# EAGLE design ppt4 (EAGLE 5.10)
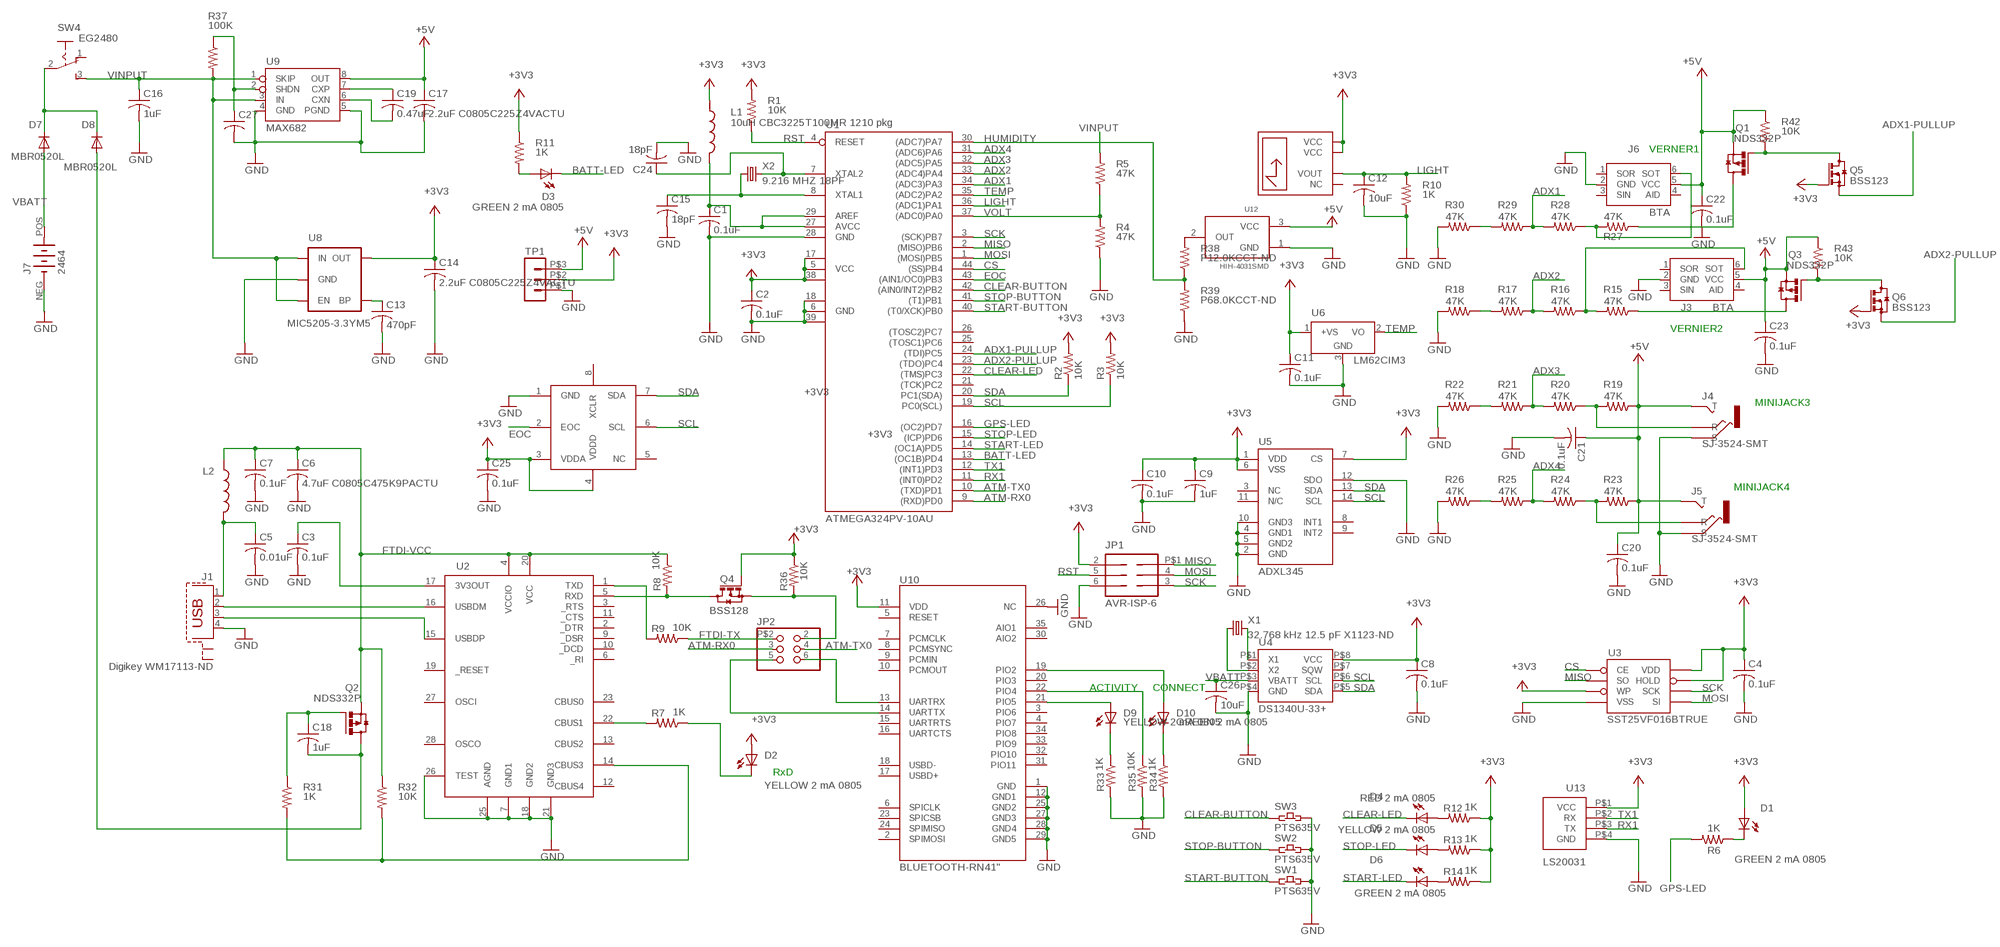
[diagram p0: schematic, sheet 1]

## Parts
C1  0.1uF  C-USC0805  [C0805]
C2  0.1uF  C-USC0805  [C0805]
C3  0.1uF  C-USC0805  [C0805]
C4  0.1uF  C-USC0805  [C0805]
C5  0.01uF  C-USC0805  [C0805]
C6  4.7uF C0805C475K9PACTU  C-USC0805  [C0805]
C7  0.1uF  C-USC0805  [C0805]
C8  0.1uF  C-USC0805  [C0805]
C9  1uF  C-USC0805  [C0805]
C10  0.1uF  C-USC0805  [C0805]
C11  0.1uF  C-USC0805  [C0805]
C12  10uF  C-USC0805  [C0805]
C13  470pF  C-USC0805  [C0805]
C14  2.2uF C0805C225Z4VACTU  C-USC0805  [C0805]
C15  18pF  C-USC1206K  [C1206K]
C16  1uF  C-USC0805  [C0805]
C17  2.2uF C0805C225Z4VACTU  C-USC0805  [C0805]
C18  1uF  C-USC0805  [C0805]
C19  0.47uF  C-USC0805  [C0805]
C20  0.1uF  C-USC0805  [C0805]
C21  0.1uF  C-USC0805  [C0805]
C22  0.1uF  C-USC0805  [C0805]
C23  0.1uF  C-USC0805  [C0805]
C24  18pF  C-USC1206K  [C1206K]
C25  0.1uF  C-USC0805  [C0805]
C26  10uF  C-USC0805  [C0805]
C27  C-USC0805  [C0805]
D1  GREEN 2 mA 0805  LED_MS  [LED-0805]
D2  YELLOW 2 mA 0805  LED_MS  [LED-0805]
D3  GREEN 2 mA 0805  LED_MS  [LED-0805]
D4  RED 2 mA 0805  LED_MS  [LED-0805]
D5  YELLOW 2 mA 0805  LED_MS  [LED-0805]
D6  GREEN 2 mA 0805  LED_MS  [LED-0805]
D7  MBR0520L  MBR0520LT  [SOD123]
D8  MBR0520L  MBR0520LT  [SOD123]
D9  YELLOW 2 mA 0805  LED_MS  [LED-0805]
D10  GREEN 2 mA 0805  LED_MS  [LED-0805]
J1  Digikey WM17113-ND  PN61729-S  [PN61729-S]
J3  BTA  DIY164  [DY164]
J4  SJ-3524-SMT  [SJ-3534-SMT]
J5  SJ-3524-SMT  [SJ-3534-SMT]
J6  BTA  DIY164  [DY164]
J7  2464  [2464R]
JP1  AVR-ISP-6  [AVR-ISP-6]
JP2  PINHD-2X3  [2X03]
L1  10uH CBC3225T100MR 1210 pkg  L-USL3216C  [L3216C]
L2  10uH CBC3225T100MR 1210 pkg  L-USL3216C  [L3216C]
Q1  NDS332P  FDN360P  [SUPER-SOT3]
Q2  NDS332P  FDN360P  [SUPER-SOT3]
Q3  NDS332P  FDN360P  [SUPER-SOT3]
Q4  BSS128  BSS123  [SOT23]
Q5  BSS123  [SOT23]
Q6  BSS123  [SOT23]
R1  10K  R-US_R0805  [R0805]
R2  10K  R-US_R0805  [R0805]
R3  10K  R-US_R0805  [R0805]
R4  47K  R-US_R0805  [R0805]
R5  47K  R-US_R0805  [R0805]
R6  1K  R-US_R0805  [R0805]
R7  1K  R-US_R0805  [R0805]
R8  10K  R-US_R0805  [R0805]
R9  10K  R-US_R0805  [R0805]
R10  1K  R-US_R0805  [R0805]
R11  1K  R-US_R0805  [R0805]
R12  1K  R-US_R0805  [R0805]
R13  1K  R-US_R0805  [R0805]
R14  1K  R-US_R0805  [R0805]
R15  47K  R-US_R0805  [R0805]
R16  47K  R-US_R0805  [R0805]
R17  47K  R-US_R0805  [R0805]
R18  47K  R-US_R0805  [R0805]
R19  47K  R-US_R0805  [R0805]
R20  47K  R-US_R0805  [R0805]
R21  47K  R-US_R0805  [R0805]
R22  47K  R-US_R0805  [R0805]
R23  47K  R-US_R0805  [R0805]
R24  47K  R-US_R0805  [R0805]
R25  47K  R-US_R0805  [R0805]
R26  47K  R-US_R0805  [R0805]
R27  47K  R-US_R0805  [R0805]
R28  47K  R-US_R0805  [R0805]
R29  47K  R-US_R0805  [R0805]
R30  47K  R-US_R0805  [R0805]
R31  1K  R-US_R0805  [R0805]
R32  10K  R-US_R0805  [R0805]
R33  1K  R-US_R0805  [R0805]
R34  1K  R-US_R0805  [R0805]
R35  10K  R-US_R0805  [R0805]
R36  10K  R-US_R0805  [R0805]
R37  100K  R-US_R0805  [R0805]
R38  P12.0KCCT-ND  R-US_R0805  [R0805]
R39  P68.0KCCT-ND  R-US_R0805  [R0805]
R42  10K  R-US_R0805  [R0805]
R43  10K  R-US_R0805  [R0805]
SW1  PTS635V  [PTS635V]
SW2  PTS635V  [PTS635V]
SW3  PTS635V  [PTS635V]
SW4  EG2480  SLIDE_SWITCH-VERT  [102-1271-EV]
TP1  MA03-1  [MA03-1]
U1  ATMEGA324PV-10AU  MEGA32-A  [TQFP44]
U2  FT232RL  [SSOP28DB]
U3  SST25VF016BTRUE  [WSON]
U4  DS1340U-33+  DS1307  [UMAX-8]
U5  ADXL345  [LGA14]
U6  LM62CIM3  LM50  [SOT23]
U7  APDS-9002  [APDS-9002]
U8  MIC5205-3.3YM5  V_REG_LDOSMD  [SOT23-5]
U9  MAX682  [SO08]
U10  BLUETOOTH-RN41"  [RN41]
U11  BMP085  [BMP085]
U12  HIH-4031SMD  HIH-4030SMD  [HIH-4030]
U13  LS20031  [DF3A-4P-BACK]
X1  32.768 kHz 12.5 pF X1123-ND  CRYSTALTC26H  [TC26H]
X2  9.216 MHZ 18PF  CRYSTALHC49U-V  [HC49U-V]

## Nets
+3V3 [SUPPLY]: C2.1 C4.1 C8.1 C9.1 C10.1 C11.1 C14.1 C25.1 D1.A D2.A JP1.2(VTG) L1.1 Q4.1(G) Q5.1(G) Q6.1(G) R1.2 R2.2 R3.2 R11.1 R12.1 R13.1 R14.1 R36.1 TP1.P$2 U1.5(VCC) U1.17(VCC1) U1.38(VCC2) U3.HOLD#(HOLD) U3.VDD U3.WP#(WP) U4.P$8(VCC) U5.1(VDD) U5.6(VSS) U5.7(CS) U6.1(+VS) U7.2(VCC) U7.3(VCC) U8.5(OUT) U10.11(VDD) U11.3(VDDA) U11.4(VDDD) U13.P$1(VCC)
+5V [SUPPLY]: C17.1 C20.1 C21.1 C22.1 C23.1 J3.5(VCC) J4.2(T) J5.2(T) J6.5(VCC) Q1.2(S) Q3.2(S) R19.1 R23.1 R42.1 R43.1 TP1.P$3 U9.8(OUT) U12.3(VCC)
ADX1: R28.2 R29.1 U1.34((ADC3)PA3)
ADX1-PULLUP: Q5.2(S) U1.24((TDI)PC5)
ADX2: R16.2 R17.1 U1.33((ADC4)PA4)
ADX2-PULLUP: Q6.2(S) U1.23((TDO)PC4)
ADX3: R20.2 R21.1 U1.32((ADC5)PA5)
ADX4: R24.2 R25.1 U1.31((ADC6)PA6)
ATM-RX0: JP2.3 U1.9((RXD)PD0)
ATM-TX0: JP2.4 U1.10((TXD)PD1)
BATT-LED: D3.C U1.13((OC1B)PD4)
CLEAR-BUTTON: SW3.1 U1.42((AIN0/INT2)PB2)
CLEAR-LED: D4.C U1.22((TMS)PC3)
CS: U1.44((SS)PB4) U3.CE#(CE)
EOC: U1.43((AIN1/OC0)PB3) U11.2(EOC)
FTDI-RX: JP2.2 Q4.2(S) R36.2
FTDI-TX: JP2.P$2 R9.1
FTDI-VCC [SUPPLY]: C6.1 C7.1 L2.1 Q2.2(S) R8.1 R32.1 U2.4(VCCIO) U2.20(VCC)
GND [SUPPLY]: C1.2 C2.2 C3.2 C4.2 C5.2 C6.2 C7.2 C8.2 C9.2 C10.2 C11.2 C12.2 C13.2 C14.2 C15.2 C16.2 C17.2 C20.2 C21.2 C22.2 C23.2 C24.2 C25.2 C26.2 C27.2 J1.4 J3.2(GND) J4.1(S) J5.1(S) J6.2(GND) J7.NEG(-) JP1.6(GND) R4.1 R10.1 R18.2 R22.2 R26.2 R30.2 R33.2 R34.2 R35.2 R39.1 SW1.2 SW2.2 SW3.2 TP1.P$1 U1.6(GND) U1.18(GND1) U1.28(GND) U1.39(GND2) U2.7(GND1) U2.18(GND2) U2.21(GND3) U2.25(AGND) U2.26(TEST) U3.VSS U4.P$4(GND) U5.2(GND) U5.4(GND1) U5.5(GND2) U5.10(GND3) U5.12(SDO) U6.3(GND) U8.2(GND) U9.4(GND) U9.5(PGND) U10.1(GND) U10.12(GND1) U10.25(GND2) U10.26(NC) U10.27(GND3) U10.28(GND4) U10.29(GND5) U11.1(GND) U12.1(GND) U13.P$4(GND)
GPS-LED: R6.2 U1.16((OC2)PD7)
HUMIDITY: R38.1 R39.2 U1.30((ADC7)PA7)
LIGHT: C12.1 R10.2 U1.36((ADC1)PA1) U7.1(VOUT)
MISO: JP1.P$1(MISO) U1.2((MISO)PB6) U3.SO
MOSI: JP1.4(MOSI) U1.1((MOSI)PB5) U3.SI
N$1: J1.2 U2.16(USBDM)
N$2: J1.3 U2.15(USBDP)
N$3: C1.1 L1.2 U1.27(AVCC) U1.29(AREF)
N$4: R38.2 U12.2(OUT)
N$5: D9.C R33.1
N$6: D3.A R11.2
N$7 [SUPPLY]: C5.1 J1.1 L2.2
N$8 [SUPPLY]: D1.C R6.1
N$9: R7.2 U2.22(CBUS1)
N$10 [SUPPLY]: D2.C R7.1
N$11: Q4.3(D) R8.2 U2.5(RXD)
N$12: R9.2 U2.1(TXD)
N$13 [SUPPLY]: C3.1 U2.17(3V3OUT)
N$14: U4.P$1(X1) X1.2
N$15: U4.P$2(X2) X1.1
N$16: D4.A R12.2
N$17: D5.A R13.2
N$18: D6.A R14.2
N$19: J3.6(SOT) R15.2 R16.1
N$20: J6.6(SOT) R27.2 R28.1
N$21: R17.2 R18.1
N$22: J4.3(R) R19.2 R20.1
N$23: R29.2 R30.1
N$24: R21.2 R22.1
N$25: J5.3(R) R23.2 R24.1
N$26: C13.1 U8.4(BP)
N$27: R25.2 R26.1
N$28 [SUPPLY]: C19.1 U9.7(CXP)
N$29 [SUPPLY]: C18.1 Q2.1(G) R31.1
N$30 [SUPPLY]: C19.2 U9.6(CXN)
N$31 [SUPPLY]: C18.2 D8.A Q2.3(D)
N$32: Q1.3(D) R27.1
N$33: C24.1 U1.7(XTAL2) X2.2
N$34: C27.1 R37.1 U9.2(SHDN)
N$35: C15.1 U1.8(XTAL1) X2.1
N$36: D9.A U10.21(PIO5)
N$37: D10.C R34.1
N$38: D10.A U10.19(PIO2)
N$39: R35.1 U10.22(PIO4)
N$40: Q1.1(G) Q5.3(D) R42.2
N$41: Q3.3(D) R15.1
N$42: Q3.1(G) Q6.3(D) R43.2
PWREN~ [SUPPLY]: R31.2 R32.2 U2.14(CBUS3)
RST: JP1.5(RST) R1.1 U1.4(RESET)
RX1: U1.11((INT0)PD2) U13.P$3(TX)
RX-BT: JP2.5 U10.14(UARTTX)
SCK: JP1.3(SCK) U1.3((SCK)PB7) U3.SCK
SCL: R3.1 U1.19(PC0(SCL)) U4.P$6(SCL) U5.14(SCL) U11.6(SCL)
SDA: R2.1 U1.20(PC1(SDA)) U4.P$5(SDA) U5.13(SDA) U11.7(SDA)
START-BUTTON: SW1.1 U1.40((T0/XCK)PB0)
START-LED: D6.C U1.14((OC1A)PD5)
STOP-BUTTON: SW2.1 U1.41((T1)PB1)
STOP-LED: D5.C U1.15((ICP)PD6)
TEMP: U1.35((ADC2)PA2) U6.2(VO)
TX1: U1.12((INT1)PD3) U13.P$2(RX)
TX-BT: JP2.6 U10.13(UARTRX)
UNSWPWR [SUPPLY]: D7.C D8.C SW4.2(COM)
VBATT [SUPPLY]: C26.1 D7.A J7.POS(+) U4.P$3(VBATT)
VINPUT [SUPPLY]: C16.1 R5.2 R37.2 SW4.3 U8.1(IN) U8.3(EN) U9.1(SKIP) U9.3(IN)
VOLT: R4.2 R5.1 U1.37((ADC0)PA0)
Unconnected: J1.S1 J1.S2 J3.1(SOR) J3.3(SIN) J3.4(AID) J6.1(SOR) J6.3(SIN) J6.4(AID) SW4.1 U1.21((TCK)PC2) U1.25((TOSC1)PC6) U1.26((TOSC2)PC7) U2.2(_DTR) U2.3(_RTS) U2.6(_RI) U2.9(_DSR) U2.10(_DCD) U2.11(_CTS) U2.12(CBUS4) U2.13(CBUS2) U2.19(_RESET) U2.23(CBUS0) U2.27(OSCI) U2.28(OSCO) U4.P$7(SQW) U5.3(NC) U5.8(INT1) U5.9(INT2) U5.11(N/C) U7.4(NC) U10.2(SPIMOSI) U10.3(PIO6) U10.4(PIO7) U10.5(RESET) U10.6(SPICLK) U10.7(PCMCLK) U10.8(PCMSYNC) U10.9(PCMIN) U10.10(PCMOUT) U10.15(UARTRTS) U10.16(UARTCTS) U10.17(USBD+) U10.18(USBD-) U10.20(PIO3) U10.23(SPICSB) U10.24(SPIMISO) U10.30(AIO2) U10.31(PIO11) U10.32(PIO10) U10.33(PIO9) U10.34(PIO8) U10.35(AIO1) U11.5(NC) U11.8(XCLR)

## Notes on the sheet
- VERNER1
- VERNIER2
- MINIJACK3
- MINIJACK4
- ACTIVITY | CONNECT
- RxD

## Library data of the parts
C1-C27 = rcl:C-US: CAPACITOR, American symbol
D1-D6 D9 D10 = machine_science:LED_MS
D7 D8 = diode:MBR0520LT: SCHOTTKY BARRIER RECTIFIER
J1 = con-berg:PN61729-S: BERG USB connector
J3 J6 = machine_science2:DIY164
J4 J5 = machine_science2:SJ-3524-SMT
J7 = machine_science2:2464
JP1 = machine_science:AVR-ISP-6: AVR ISP-6 Serial Programming Header
JP2 = pinhead:PINHD-2X3: PIN HEADER
L1 L2 = rcl:L-US: INDUCTOR, American symbol
Q1-Q3 = transistor-power:FDN360P: Single P-Channel, PowerTrench (R) MOSFET Source: http://www.fairchildsemi.com/ds/FD/FDN360P.pdf
Q4-Q6 = transistor-small-signal:BSS123: N-CHANNEL MOS FET
R1-R39 R42 R43 = rcl:R-US_: RESISTOR, American symbol
SW1-SW3 = machine_science:PTS635
SW4 = machine_science:SLIDE_SWITCH
TP1 = con-lstb:MA03-1: PIN HEADER
U1 = atmel:MEGA32: MICROCONTROLLER 32 Kbytes FLASH 2 Kbytes SRAM 1 Kbytes EEPROM USART 8-channel 10 bit ADC Source: www.atmel.com .. doc2503.pdf
U2 = SparkFunEagle-6-6-07:FT232RL: USB UART FT232RL 4th Generation USB UART (USB <-> Serial) Controller. Spark Fun Electronics SKU : COM-00650
U3 = machine_science:SST25VF016BTRUE
U4 = SparkFun:DS1307
U5 = SparkFun:ADXL345
U6 = linear:LM50: SOT-23 Single-Supply Centigrade Temperature Sensor Vout = (10mV/°C x Temp °C) +5mmmV Source: http://cache.national.com/ds/LM/LM50.pdf
U7 = machine_science:APDS-9002
U8 = SparkFun:V_REG_LDO: Voltage Regulator LDO Standard 150mA LDO voltage regulator in SOT-23 layout. Micrel part MIC5205. BP (by-pass) pin is used to lower output noise with 470pF cap.
U9 = max682:MAX682
U10 = SparkFun:BLUETOOTH-RN41
U11 = SparkFun-20100301:BMP085
U12 = SparkFun-20100301:HIH-4030: Humidity Sensor
U13 = machine_science:LS20031
X1 = SparkFun:CRYSTAL: Crystals
X2 = crystal:CRYSTAL: CRYSTAL

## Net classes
0 SIGNAL: width 0.203 mm, drill 0.203 mm, clearance 0.203 mm
1 SUPPLY: width 0.356 mm, drill 0.203 mm, clearance 0.203 mm

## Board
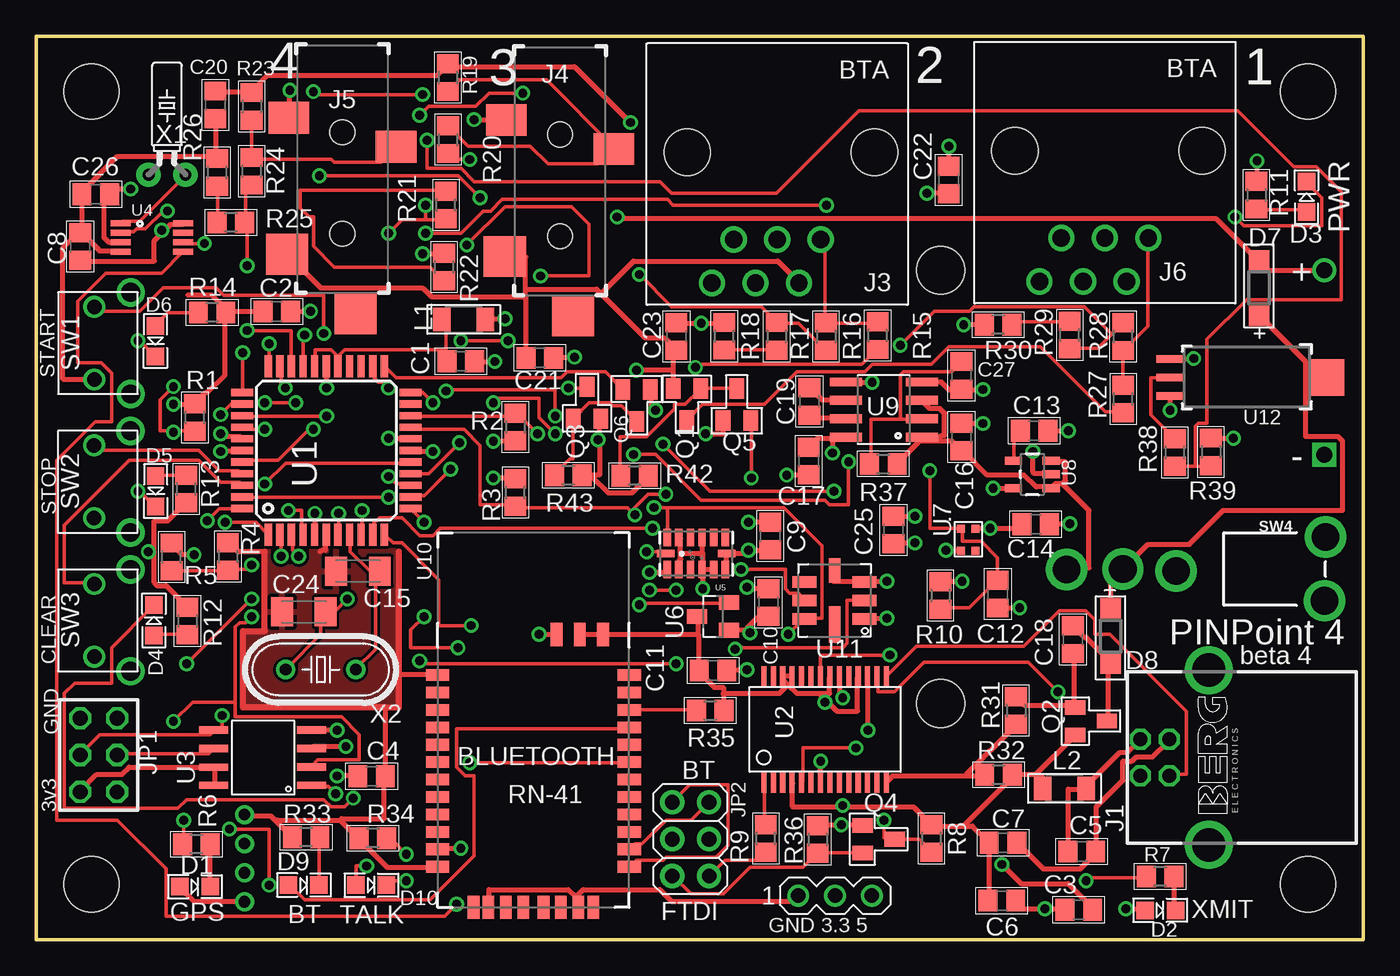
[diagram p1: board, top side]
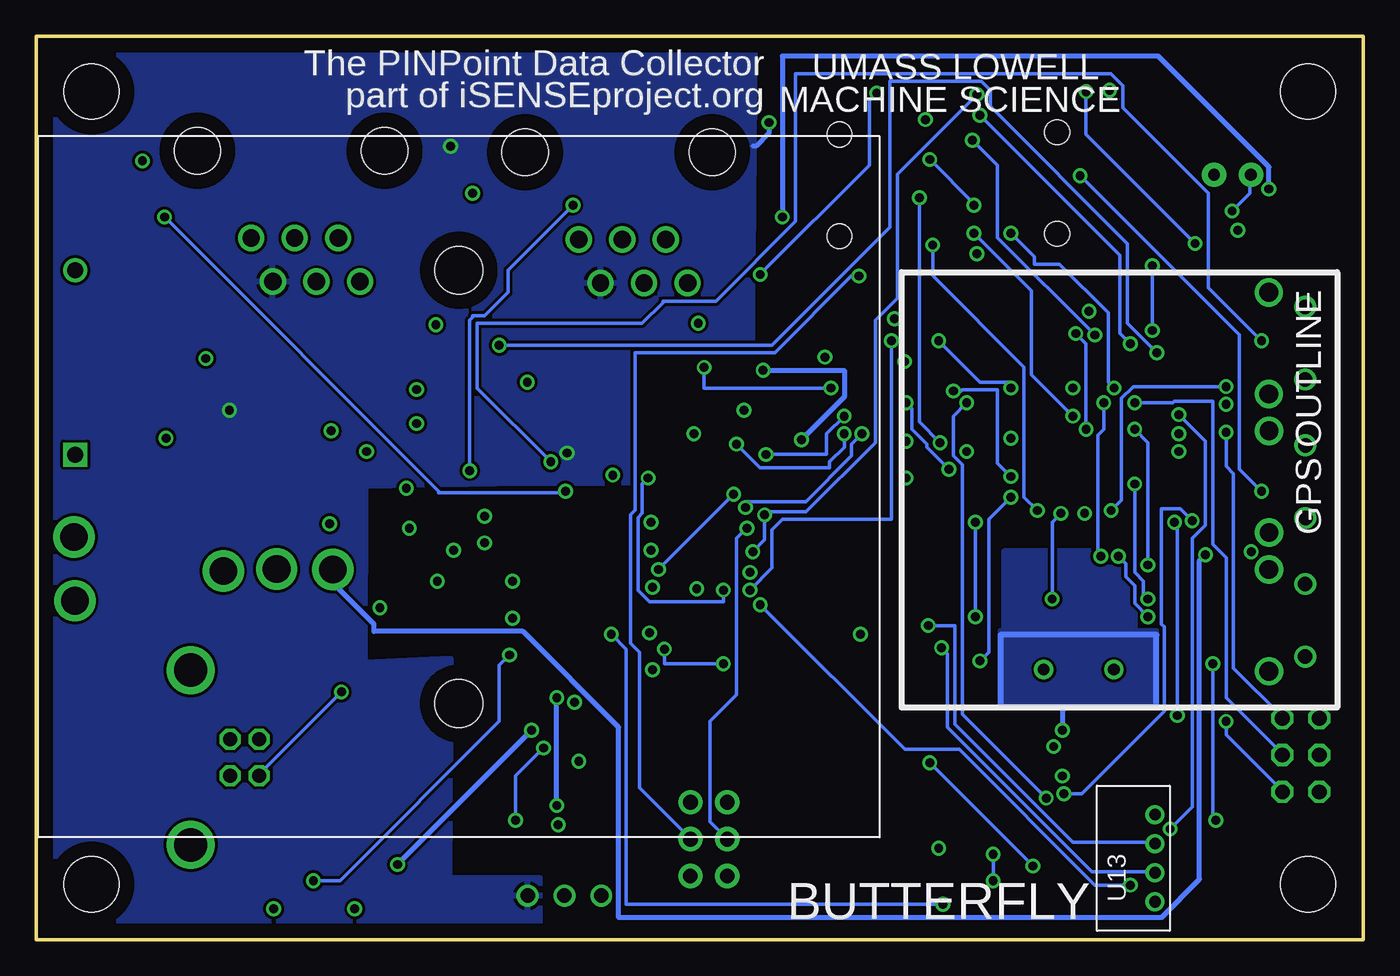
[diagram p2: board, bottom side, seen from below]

Size 91.44 x 62.23 mm. Coordinates in mm from the lower left corner, seen from the top.
Outline: 0,0 0,62.23 91.44,62.23 91.44,0 0,0
Copper layers (1*2+3*16): Top 0.035mm / dielectric 1.5mm / $gnd 0.035mm / dielectric 0.15mm / $+3v3 0.035mm / dielectric 0.2mm / Bottom 0.035mm
Design rules "default *": minimum track width 10mil, minimum drill 24mil, track to track 8mil, track to pad 8mil, pad to pad 8mil, via to via 8mil, smd to smd 8mil, copper to edge 40mil, drill to drill 8mil, minimum pad ring 10mil, minimum via ring 8mil, stop-mask expansion 4mil, vias tented up to drill 0mil, thermal gap 10mil
Holes 3.81 mm at 3.81,3.81 3.81,58.42 87.63,3.81 87.63,58.42
tRestrict: area -0.2,-0.2 to 7.8,7.8; area -0.2,54.4 to 7.8,62.4; area 83.6,-0.2 to 91.6,7.8; area 83.6,54.4 to 91.6,62.4

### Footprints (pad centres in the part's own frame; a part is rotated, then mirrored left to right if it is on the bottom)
C0805 = smd 1.3 x 1.5: 1 -0.95,0; 2 0.95,0
C1206K = smd 1.5 x 2: 1 -1.5,0; 2 1.5,0
LED-0805 = smd 1.2 x 1.2: A 0,-1.05; C 0,1.05
SOD123 = smd 1.4 x 1.4: A 1.9,0; C -1.9,0
PN61729-S = drill 0.95 octagon: 1 1.25,4.71; 2 -1.25,4.71; 3 -1.25,2.71; 4 1.25,2.71 | drill 2.3 pad 2.9 round: S1 -6.02,0; S2 6.02,0
DY164 = drill 1.2 round: 1 4.5,3; 2 3,0; 3 1.5,3; 4 0,0; 5 -1.5,3; 6 -3,0 | hole 3.2: 6.2,-6; -6.7,-6
SJ-3534-SMT = smd 2.2 x 2.8: 1 0,-3.7; 3 2,3.7 | smd 2.8 x 2.9: 2 9.4,-3.8; 10 13.5,0.9 | hole 1.7: 1,0; 8,0
2464R = drill 1.1 square: NEG 26.42,2.225 | drill 1.1 round: POS 26.42,14.925 | hole 3.3: 0,14.925; 0,-14.925
AVR-ISP-6 = drill 1.016 octagon: 2 -2.54,1.27; 3 0,-1.27; 4 0,1.27; 5 2.54,-1.27; 6 2.54,1.27 | drill 1 octagon: P$1 -2.54,-1.27
2X03 = drill 1.016 pad 1.676 round: 2 -2.54,1.27; 3 0,-1.27; 4 0,1.27; 5 2.54,-1.27; 6 2.54,1.27 | drill 1 pad 1.676 round: P$2 -2.54,-1.27
L3216C = smd 1.2 x 1.6: 1 -1.5,0; 2 1.5,0
SUPER-SOT3 = smd 1 x 1.4: 1 -0.95,-1.1; 2 0.95,-1.1; 3 0,1.1
SOT23 = smd 1 x 1.4: 1 -0.95,-1.1; 2 0.95,-1.1; 3 0,1.1
R0805 = smd 1.3 x 1.5: 1 -0.95,0; 2 0.95,0
PTS635V = drill 1 round: 1 -2.5,0; 2 2.5,0 | drill 1.3 round: P$1 -3.5,2.5; P$2 3.5,2.5
102-1271-EV = drill 1.9 round: 1 -0.14,10.28; 2 0,13.96; 3 -0.03,17.82; P$1 2.2,0; P$2 -2.19,0.05
MA03-1 = drill 1 round: P$1 -2.54,0; P$2 0,0; P$3 2.54,0
TQFP44 = smd 1.5 x 0.5: 1 -5.8,4; 2 -5.8,3.2; 3 -5.8,2.4; 4 -5.8,1.6; 5 -5.8,0.8; 6 -5.8,0; 7 -5.8,-0.8; 8 -5.8,-1.6; 9 -5.8,-2.4; 10 -5.8,-3.2; 11 -5.8,-4; 23 5.8,-4; 24 5.8,-3.2; 25 5.8,-2.4; 26 5.8,-1.6; 27 5.8,-0.8; 28 5.8,0; 29 5.8,0.8; 30 5.8,1.6; 31 5.8,2.4; 32 5.8,3.2; 33 5.8,4 | smd 0.5 x 1.5: 12 -4,-5.8; 13 -3.2,-5.8; 14 -2.4,-5.8; 15 -1.6,-5.8; 16 -0.8,-5.8; 17 0,-5.8; 18 0.8,-5.8; 19 1.6,-5.8; 20 2.4,-5.8; 21 3.2,-5.8; 22 4,-5.8; 34 4,5.8; 35 3.2,5.8; 36 2.4,5.8; 37 1.6,5.8; 38 0.8,5.8; 39 0,5.8; 40 -0.8,5.8; 41 -1.6,5.8; 42 -2.4,5.8; 43 -3.2,5.8; 44 -4,5.8
SSOP28DB = smd 0.348 x 1.397: 1 -4.225,-3.656; 2 -3.575,-3.656; 3 -2.925,-3.656; 4 -2.275,-3.656; 5 -1.625,-3.656; 6 -0.975,-3.656; 7 -0.325,-3.656; 8 0.325,-3.656; 9 0.975,-3.656; 10 1.625,-3.656; 11 2.275,-3.656; 12 2.925,-3.656; 13 3.575,-3.656; 14 4.225,-3.656; 15 4.225,3.656; 16 3.575,3.656; 17 2.925,3.656; 18 2.275,3.656; 19 1.625,3.656; 20 0.975,3.656; 21 0.325,3.656; 22 -0.325,3.656; 23 -0.975,3.656; 24 -1.625,3.656; 25 -2.275,3.656; 26 -2.925,3.656; 27 -3.575,3.656; 28 -4.225,3.656
WSON = smd 2 x 0.5: CE# -3.29,1.595; HOLD# 3.46,0.345; SCK 3.46,-0.945; SI 3.46,-2.215; SO -3.29,0.325; VDD 3.46,1.595; VSS -3.29,-2.215; WP# -3.29,-0.945
UMAX-8 = smd 1.35 x 0.4: P$1 -2.15,0.975; P$2 -2.15,0.325; P$3 -2.15,-0.325; P$4 -2.15,-0.975; P$5 2.15,-0.975; P$6 2.15,-0.325; P$7 2.15,0.325; P$8 2.15,0.975
LGA14 = smd 0.5 x 1.2: 1 2,1.1; 2 1.2,1.1; 3 0.4,1.1; 4 -0.4,1.1; 5 -1.2,1.1; 6 -2,1.1; 8 -2,-1.1; 9 -1.2,-1.1; 10 -0.4,-1.1; 11 0.4,-1.1; 12 1.2,-1.1; 13 2,-1.1 | smd 1.2 x 0.5: 7 -2.1,0; 14 2.1,0
APDS-9002 = smd 0.55 x 0.55: 1 -0.5,0.75; 2 0.5,0.75; 3 -0.5,-0.75; 4 0.5,-0.75
SOT23-5 = smd 0.55 x 1.2: 1 -0.95,-1.3; 2 0,-1.3; 3 0.95,-1.3; 4 0.95,1.3; 5 -0.95,1.3
SO08 = smd 0.61 x 2.21: 1 -1.905,-2.616; 2 -0.635,-2.616; 3 0.635,-2.616; 4 1.905,-2.616; 5 1.905,2.616; 6 0.635,2.616; 7 -0.635,2.616; 8 -1.905,2.616
RN41 = smd 0.8 x 1.6: 1 -6.6,-6.6; 2 -5.4,-6.6; 3 -4.2,-6.6; 4 -3,-6.6; 5 -1.8,-6.6; 6 -0.6,-6.6; 7 0.6,-6.6; 8 1.8,-6.6; 9 3,-6.6; 10 4.2,-6.6; 11 5.4,-6.6; 12 6.6,-6.6; 13 6.6,6.6; 14 5.4,6.6; 15 4.2,6.6; 16 3,6.6; 17 1.8,6.6; 18 0.6,6.6; 19 -0.6,6.6; 20 -1.8,6.6; 21 -3,6.6; 22 -4.2,6.6; 23 -5.4,6.6; 24 -6.6,6.6 | smd 1.6 x 0.8: 25 -9.4,4.8; 26 -9.4,3.2; 27 -9.4,1.6; 28 9.4,3.1; 29 9.4,-3.1; 30 9.4,-4.122; 31 9.4,-1.9; 32 9.4,-0.7; 33 9.4,0.7; 34 9.4,1.9; 35 9.4,4.122
BMP085 = smd 1.67 x 0.8: 1 -2.065,1.27; 2 -2.065,0; 3 -2.065,-1.27; 5 2.065,-1.27; 6 2.065,0; 7 2.065,1.27 | smd 0.8 x 1.67: 4 0,-2.065 | smd 0.8 x 2.5: 8 0,1.65
HIH-4030 = smd 0.508 x 1.778: 1 -1.27,-5.08; 2 0,-5.08; 3 1.27,-5.08 | smd 2.54 x 2.286: NC 0,5.842
DF3A-4P-BACK = drill 0.8 round: P$1 3,0; P$2 1,0; P$3 -1,0; P$4 -3,0
TC26H = drill 0.813 pad 1.676 round: 1 -1.27,0; 2 1.27,0
HC49U-V = drill 0.813 round: 1 -2.413,0; 2 2.413,0

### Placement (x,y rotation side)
C1  29.26,39.84 0 top
C2  16.58,43.27 0 top
C3  71.84,2.07 180 top
C4  23.11,11.25 0 top
C5  72.05,6.07 0 top
C6  66.54,2.69 0 top
C7  66.62,6.68 0 top
C8  3.03,47.75 90 top
C9  50.58,27.8 90 top
C10  50.46,23.23 90 top
C11  46.63,18.54 180 top
C12  66.25,23.8 270 top
C13  68.76,35.06 0 top
C14  68.87,28.61 0 top
C15  22.17,25.39 180 top
C16  63.75,34.62 90 top
C17  53.23,32.98 270 top
C18  71.43,20.66 90 top
C19  53.27,37.07 90 top
C20  12.34,57.51 270 top
C21  34.7,40.08 0 top
C22  62.88,52.33 270 top
C23  44.11,41.55 90 top
C24  18.44,22.58 180 top
C25  59.07,28.23 90 top
C26  4.1,51.34 180 top
C27  63.75,38.88 270 top
D1  10.94,3.65 270 top
D2  77.45,2.02 270 top
D3  87.54,51.17 0 top
D4  8.1,22 0 top
D5  8.23,30.89 180 top
D6  8.21,41.22 180 top
D7  84.25,44.91 90 top
D8  74.03,20.91 270 top
D9  18.43,3.76 270 top
D10  23.08,3.75 270 top
J1  80.8,12.55 90 top
J3  51.06,48.23 180 top
J4  36.08,56.46 270 top
J5  21.1,56.62 270 top
J6  73.63,48.34 180 top
J7  62.33,31.19 0 top
JP1  4.3,12.72 90 top
JP2  45.09,6.93 90 top
L1  29.45,42.73 180 top
L2  70.86,10.42 0 top
Q1  44.84,36.87 180 top
Q2  72.68,15.06 270 top
Q3  37.95,36.98 0 top
Q4  58.05,6.92 270 top
Q5  48.27,36.87 0 top
Q6  41.37,36.81 180 top
R1  10.94,35.97 90 top
R2  33.01,35.31 270 top
R3  33.02,30.81 90 top
R4  13.21,26.4 270 top
R5  9.32,26.37 90 top
R6  11.03,6.57 180 top
R7  77.43,4.35 180 top
R8  61.68,6.97 270 top
R9  50.27,6.97 90 top
R10  62.3,23.71 270 top
R11  84.08,51.28 270 top
R12  10.42,21.95 270 top
R13  10.34,31.04 90 top
R14  12.12,43.2 180 top
R15  57.98,41.61 90 top
R16  54.42,41.55 270 top
R17  51.02,41.56 270 top
R18  47.41,41.57 90 top
R19  28.36,59.38 270 top
R20  28.37,55.11 270 top
R21  28.23,50.61 90 top
R22  28.11,46.33 90 top
R23  14.85,57.41 270 top
R24  14.84,52.93 270 top
R25  13.42,49.4 180 top
R26  12.47,52.86 90 top
R27  74.9,37.24 90 top
R28  74.89,41.54 90 top
R29  71.21,41.65 90 top
R30  66.28,42.36 180 top
R31  67.51,15.78 270 top
R32  66.3,11.36 180 top
R33  18.6,7.06 180 top
R34  23.18,6.99 180 top
R35  46.44,15.79 0 top
R36  53.85,6.91 270 top
R37  58.37,32.77 0 top
R38  78.46,33.56 90 top
R39  80.95,33.61 270 top
R42  41.23,31.96 180 top
R43  36.65,31.99 180 top
SW1  4,41.09 270 top
SW2  3.99,31.55 270 top
SW3  4,22 270 top
SW4  88.83,25.53 90 top
TP1  55.04,3.03 0 top
U1  19.99,33.7 90 top
U2  54.36,14.48 0 top
U3  15.7,12.23 180 top
U4  7.97,48.37 0 top
U5  45.48,26.6 180 top
U6  46.63,22.26 90 top
U7  64.23,27.55 0 top
U8  68.63,32.06 90 top
U9  58.4,36.52 90 top
U10  34.26,11.63 270 top
U11  55.01,23.37 180 top
U12  83.16,38.72 270 top
U13  14.34,5.61 270 top
X1  9.01,52.69 0 top
X2  19.61,18.61 180 top

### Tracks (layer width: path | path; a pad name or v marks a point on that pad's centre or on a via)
+3V3  (via drill 0.61)
  Top 0.356: 8.74,48.77 8.13,48.16 8.13,46.74 3.05,46.74 C8.1 | 8.74,48.77 9.25,49.28 10.06,49.28 U4.P$8 | R14.1 13.01,43.18 13.01,38.91 11.79,37.69 11.68,37.69 10.97,36.98 R1.2 10.77,36.88 v9.45,36.88 | C2.1 15.54,43.28 13.21,43.28 R14.1 | 10.46,44.4 12.09,44.4 13.11,43.38 R14.1 | U5.6 47.55,25.5 47.55,26.52 U5.7 47.75,26.62 48.97,26.62 49.17,26.82 | 8.13,26.72 8.13,28.85 9.04,28.85 10.26,30.07 R13.1 | 8.13,26.72 8.13,24.59 8.33,24.38 8.94,24.38 10.36,22.96 R12.1 | Q4.1 56.9,7.92 v55.47,7.92 53.95,7.92 R36.1 | U3.VDD 12.29,10.67 12.29,11.79 U3.HOLD# 12.09,11.89 6.4,11.89 5.89,11.38 4.17,11.38 3.05,10.26 JP1.2 | D1.A 9.96,3.56 10.87,2.64 14.33,2.64 U13.P$1 | v42.27,25.3 43.28,25.3 43.38,25.4 U5.1 | v75.08,2.13 76.2,2.13 76.3,2.03 D2.A | v20.73,11.28 22.15,11.28 C4.1 | v12.7,34.85 12.9,34.65 14.02,34.65 14.12,34.54 U1.38 | v84.12,53.65 84.12,52.32 R11.1 | v29.26,6.3 27.74,6.3 U10.11 | v21.34,13.31 19.1,13.31 19,13.21 U3.WP# | 8.13,26.72 v7.72,26.72 | 8.74,48.77 v8.64,48.87 | U11.4 54.97,25.4 54.97,24.69 57,24.69 U11.3 57.2,24.69 v58.62,24.69 | v62.69,26.82 63.7,26.82 U7.3 | v48.97,18.59 47.65,18.59 C11.1 | v60.55,27.33 59.13,27.33 C25.1 | U7.2 64.82,28.35 v65.73,28.35 67.87,28.35 67.87,28.55 C14.1 | v65.94,31.09 67.26,31.09 U8.5 | U6.1 47.75,21.34 48.97,21.34 v49.17,21.13 48.97,21.44 49.78,22.25 50.39,22.25 C10.1 | v32.31,42.77 30.99,42.77 L1.1 | 49.17,26.82 50.49,26.82 C9.1 | v42.67,36.47 42.47,36.68 42.37,36.68 42.37,37.9 Q6.1 | v46.13,34.85 47.35,34.85 47.35,35.76 Q5.1 | 49.17,26.82 v49.07,26.82 | v27.33,33.63 25.81,33.63 U1.17 | v19.2,29.36 19.2,27.94 U1.5 | v31.5,31.8 32.92,31.8 R3.2 | v31.5,34.34 32.92,34.34 R2.2
+5V  (via drill 0.61)
  Top 0.356: C20.1 12.39,58.42 14.83,58.42 R23.1 14.94,58.52 15.95,59.54 27.64,59.54 28.35,60.25 R19.1 28.45,60.15 37.08,60.15 v40.95,56.29 | 33.73,44.81 33.73,47.04 32.31,47.04 J4.2 | 33.73,44.3 33.73,44.81 | 33.73,44.3 33.73,40.13 C21.1 | 38.91,44.5 38.61,44.81 33.73,44.81 | 38.91,44.5 41.96,41.45 43.28,41.45 44.09,40.64 C23.1 43.89,40.64 43.89,39.22 | J5.2 17.37,47.14 19.61,44.91 26.62,44.91 27.23,44.3 33.73,44.3 | C17.1 53.85,34.54 55.78,34.54 U9.8 54.86,34.44 v54.86,33.53 | v62.89,54.66 62.89,53.34 C22.1 | v78.13,36.47 78.13,37.39 U12.3 | 38.91,44.5 41.15,46.74 51.1,46.74 52.53,45.31 J3.5 | 43.89,39.22 43.89,38 Q1.2 | 38.81,34.44 38.81,32 38.3,32 | 38.81,34.44 38.81,35.87 Q3.2 | 38.3,32 37.69,32 R43.1 | R42.1 42.16,31.9 41.05,30.79 39.42,30.79 38.3,31.9 38.3,32 | 43.89,39.22 v41.35,39.22 | v38.71,34.44 38.81,34.44
  Bottom 0.356: v40.95,56.29 40.95,55.58 41.86,54.66 42.03,54.66 | v41.35,39.22 35.76,39.22 35.76,37.39 v38.71,34.44
  pour Bottom: 41.96,62.24 42.21,31.48 59.88,31.41 68.78,31.24 68.81,19.13 62.9,19.38 63,4.25 56.75,4.25 56.75,0 91.26,0 91.26,62.24
ADX1  (via drill 0.61)
  Top 0.254: 74.12,41.71 73.15,40.74 71.32,40.74 R29.1 | 74.12,41.71 74.88,42.47 R28.2 | v14.22,40.44 14.22,37.8 U1.34 | v59.54,40.95 61.87,43.28 64.31,43.28 64.62,43.59 72.24,43.59 74.12,41.71
  Bottom 0.254: v14.22,40.44 16.26,42.47 16.26,47.95 25.7,57.4 25.7,58.52 26.31,59.13 32.61,59.13 32.61,49.07 40.74,40.95 v59.54,40.95
ADX1-PULLUP  (via drill 0.61)
  Top 0.254: v49.28,31.8 49.28,35.76 Q5.2 | v42.27,24.08 v44.09,24.08 | v29.26,41.25 v32.51,41.25 | v24.28,38 23.88,38.41 23.57,38.41 23.27,38.71 23.27,39.42 U1.24
  Bottom 0.254: v49.28,31.8 49.68,31.39 49.68,29.36 49.99,29.06 49.99,24.08 49.17,23.27 44.09,23.27 v44.09,24.08 | v42.27,24.08 40.74,25.6 40.74,28.25 40.03,28.96 32.51,28.96 v32.51,41.25 | v29.26,41.25 26.42,38.41 24.28,38.41 v24.28,38
ADX2  (via drill 0.61)
  Top 0.254: v16.05,41.05 16.05,39.52 U1.33 | v26.42,56.79 27.03,57.4 30.28,57.4 31.19,58.32 v33.53,58.32 | v41.55,45.82 43.79,43.59 49.99,43.59 51,42.57 R17.1 51.1,42.47 52.53,42.47 54.36,40.64 R16.2
  Bottom 0.254: v16.05,41.05 16.76,41.76 16.76,47.14 v26.42,56.79 | v33.53,58.32 34.04,57.81 34.04,53.34 v41.55,45.82
ADX2-PULLUP
  Top 0.254: Q6.2 40.34,38 39.22,39.12 36.58,39.12 36.17,38.71 24.79,38.71 24.08,39.42 U1.23
ADX3  (via drill 0.61)
  Top 0.254: v17.17,38 16.87,38 16.87,39.42 U1.32 | v24.28,48.67 25.2,49.58 26.82,49.58 | 26.82,49.58 28.14,49.58 R21.1 | v29.87,53.75 28.85,53.75 28.45,54.15 R20.2 | 26.82,49.58 v26.82,50.6
  Bottom 0.254: v17.17,38 17.58,38.41 17.58,43.18 20.93,46.53 22.66,46.53 22.66,47.04 v24.28,48.67 | v29.87,53.75 26.82,50.7 v26.82,50.6
ADX4  (via drill 0.61)
  Top 0.254: R24.2 14.83,51.92 14.43,51.92 14.43,49.48 R25.1 14.33,49.28 14.53,49.28 v14.53,46.43 | v14.53,41.96 17.58,41.96 17.58,39.52 U1.31
  Bottom 0.254: v14.53,41.96 v14.53,46.43
ATM-RX0  (via drill 0.61)
  Top 0.254: v22.45,29.57 22.45,27.94 U1.9 | v29.67,47.85 32.31,50.49 36.88,50.49 38.1,49.28 38.1,45.72 v34.75,45.72
  Bottom 0.254: v22.45,29.57 23.37,30.48 23.37,39.42 29.67,45.72 v29.67,47.85 | v34.75,45.72 35.26,45.72 40.54,40.44 50.19,40.44 50.19,29.57 50.49,29.26 50.49,20.42 49.89,19.81 49.89,10.46 46.43,7.01 JP2.3
ATM-TX0  (via drill 0.61)
  Top 0.254: v42.47,28.35 27.84,28.35 27.33,27.84 26.42,27.84 25.2,29.06 23.67,29.06 23.47,28.85 23.27,28.85 23.27,27.94 U1.10
  Bottom 0.254: v42.47,28.35 43.18,27.64 43.18,16.87 45.01,15.04 45.01,8.13 43.89,7.01 JP2.4
BATT-LED  (via drill 0.61)
  Top 0.254: v82.6,49.78 83.21,49.17 88.59,49.17 88.59,51.1 87.58,52.12 D3.C | v54.97,30.89 46.43,30.89 v43.18,34.14 | v35.76,34.85 34.65,35.97 34.65,37.29 31.8,37.29 v31.5,36.98 | v28.55,32.41 26.72,30.58 25.81,30.58 U1.13
  Bottom 0.254: v54.97,30.89 54.97,30.79 63.7,30.79 63.7,30.89 v82.6,49.78 | v43.18,34.14 41.55,32.51 36.78,32.51 36.78,32.92 35.76,33.93 v35.76,34.85 | v31.5,36.98 31.09,36.58 31.09,35.15 30.07,34.14 30.07,33.93 v28.55,32.41
CLEAR-BUTTON
  Top 0.254: U1.42 14.12,31.39 14.02,31.5 12.7,31.5 11.18,33.02 6.4,33.02 1.93,28.55 1.93,24.59 3.96,24.59 SW3.1
CLEAR-LED  (via drill 0.61)
  Top 0.254: v21.84,9.75 21.23,9.14 20.32,9.14 19.81,9.65 10.36,9.65 9.75,9.04 1.93,9.04 1.93,16.97 2.64,17.68 5.18,17.68 5.18,20.12 8.03,22.96 D4.C | v27.33,36.98 26.62,37.69 25.81,37.69 U1.22
  Bottom 0.254: v21.84,9.75 27.64,15.54 27.64,32.72 28.25,33.33 28.25,36.07 v27.33,36.98
CS  (via drill 0.61)
  Top 0.254: v11.79,28.85 12.6,29.67 14.12,29.67 U1.44 | v20.62,10.06 20.12,10.57 19,10.57 U3.CE#
  Bottom 0.254: v11.79,28.85 12.6,29.67 13.92,29.67 13.92,21.74 13.72,21.54 13.72,15.75 19.41,10.06 v20.62,10.06
EOC  (via drill 0.61)
  Top 0.254: v24.28,30.48 14.22,30.48 U1.43 | v26.42,19.2 26.62,19 v44.09,19 | v48.16,20.02 48.26,20.12 55.58,20.12 55.88,20.42 55.88,23.37 57,23.37 U11.2
  Bottom 0.254: v24.28,30.48 25.81,28.96 25.81,19.81 v26.42,19.2 | v44.09,19 48.16,19 v48.16,20.02
FTDI-RX
  Top 0.254: Q4.2 56.9,5.99 53.95,5.99 R36.2 53.75,5.89 52.83,4.98 49.17,4.98 47.35,3.15 45.11,3.15 43.89,4.37 JP2.2
FTDI-TX
  Top 0.254: R9.1 50.19,5.99 49.68,5.49 47.45,5.49 46.43,4.47 JP2.P$2
FTDI-VCC  (via drill 0.61)
  Top 0.356: 68.89,11.38 71.53,14.02 Q2.2 | 68.89,11.38 67.26,11.38 R32.1 67.26,11.18 64.01,7.92 64.01,7.82 | L2.1 69.29,10.46 69.29,11.28 68.99,11.28 68.89,11.38 | C6.1 65.63,2.74 65.63,6.6 C7.1 65.53,6.81 64.52,7.82 64.01,7.82 | 55.58,9.14 60.45,9.14 R8.1 61.77,7.82 64.01,7.82 | 55.58,9.14 52.12,9.14 52.12,10.77 U2.4 | v55.58,16.66 55.37,16.66 55.37,18.09 U2.20 | 55.58,9.14 v55.58,9.25
  Bottom 0.356: v55.58,9.25 v55.58,16.66
GND  (via drill 0.61)
  Top 0.356: 44.4,26.62 44.4,27.64 44.3,27.64 U5.12 | 44.4,26.62 44.4,26.21 44.3,26.11 44.3,25.5 U5.2 | U5.4 45.92,25.5 46.63,25.5 U5.5 | 45.92,26.62 45.92,25.6 U5.4 | 45.92,26.62 45.92,27.64 U5.10 | 44.4,26.62 45.92,26.62 | R4.1 13.31,27.33 13.92,26.72 15.75,26.72 | U1.6 19.91,27.84 19.91,26.82 19.71,26.82 19.53,26.74 | 24.08,16 24.08,11.28 C4.2 23.98,11.18 23.98,8.33 21.03,8.33 20.93,8.23 | U10.1 27.64,18.29 25,18.29 | U2.25 52.02,18.19 51.51,18.19 U2.26 51.41,17.98 51.82,17.58 | 54.05,16.97 52.43,16.97 51.82,17.58 | 54.05,16.97 54.66,16.97 54.66,18.09 U2.21 | 54.46,16.46 54.05,16.87 54.05,16.97 | 54.46,16.46 55.17,15.75 56.59,15.75 56.59,18.09 U2.18 | 45.62,21.03 45.62,18.59 C11.2 45.72,18.39 46.74,17.37 47.35,17.37 47.35,16.97 | 45.62,21.03 45.62,22.25 U6.3 | 47.35,16.97 47.35,15.85 R35.2 | 45.62,21.03 39.12,21.03 U10.25 38.91,21.03 37.49,21.03 U10.26 | 51.82,17.58 51.21,16.97 47.35,16.97 | C20.2 12.39,56.49 12.39,53.85 R26.2 12.29,53.95 5.59,53.95 3.15,51.51 C26.2 3.15,51.31 3.15,48.87 3.05,48.87 C8.2 | U4.P$4 5.79,47.35 5.69,47.45 4.37,47.45 3.15,48.67 3.05,48.67 C8.2 | 37.19,2.95 37.29,2.85 37.29,2.23 U10.28 | 37.19,2.95 36.68,3.45 31.19,3.45 31.19,2.23 U10.29 | C7.2 67.67,6.6 69.39,4.88 71.93,4.88 73.05,5.99 C5.2 73.05,6.2 73.05,9.14 74.88,10.97 74.88,12.29 75.49,12.29 75.79,12.6 76.91,12.6 78.03,13.72 J1.4 | C6.2 67.56,2.64 68.07,2.13 v69.49,2.13 70.81,2.13 C3.2 | C23.2 44.2,42.47 v45.82,42.47 47.35,42.47 R18.2 | v54.05,12.29 54.05,10.87 U2.7 | 16.56,8.13 16.15,8.53 14.43,8.53 U13.P$4 | 16.56,8.13 17.58,7.11 R33.2 | v12.7,33.63 14.12,33.63 U1.39 | 20.93,8.23 22.15,7.01 R34.2 22.25,6.81 22.35,6.81 24.18,4.98 27.64,4.98 U10.12
  Top 0.356: 20.93,8.23 16.66,8.23 16.56,8.13 | v26.62,47.24 28.04,47.24 R22.2 | v34.65,21.03 35.76,21.03 U10.27 | v20.73,14.43 19,14.43 U3.VSS | v17.48,58.52 17.48,56.69 J5.1 | v30.18,56.49 32.31,56.49 J4.1 | 37.19,2.95 37.69,3.45 42.98,3.45 43.79,2.64 52.12,2.64 52.43,2.95 TP1.P$1 | C8.2 2.85,48.67 1.83,47.65 1.83,38.61 3.96,38.61 SW1.2 | 54.46,16.46 v54.36,16.36 | v63.8,24.69 62.38,24.69 R10.1 | v60.55,29.16 59.13,29.16 C25.2 | v67.77,22.86 66.34,22.86 C12.2 | v58.62,22.15 57.1,22.15 U11.1 | v68.68,33.63 68.68,32.21 68.78,32.11 69.9,32.11 U8.2 | v31.6,39.83 30.28,39.83 C1.2 | v48.97,24.28 49.07,24.18 50.39,24.18 C10.2 | v49.07,28.75 50.49,28.75 C9.2 | v51.71,32 53.14,32 C17.2 | v71.12,35.05 69.8,35.05 C13.2 | v63.91,42.37 R30.2 | v82.5,34.54 80.97,34.54 R39.1 | v61.37,51.41 62.79,51.41 C22.2 | v79.76,40.03 78.13,40.03 U12.1 | v57.61,38.41 55.88,38.41 U9.5 | v45.92,24.18 45.92,25.4 U5.4 | v37.08,40.13 35.66,40.13 C21.2 | v20.02,38 20.02,39.42 U1.28 | v24.28,34.54 25.7,34.54 U1.18 | v18.9,43.28 17.58,43.28 C2.2 | v71.22,28.65 69.9,28.65 C14.2 | v65.23,37.9 63.8,37.9 C27.2 63.6,37.9 62.89,37.9 62.38,38.41 61.06,38.41 U9.4 | v65.23,35.56 63.8,35.56 C16.2
  Top 0.406: 15.75,26.75 15.75,26.72 15.75,21.25 14.25,21.25 14.25,16 24.08,16 25,16 25,18.29 25,26.75
  Bottom 0.356: 20.73,16 v20.73,14.43
  Bottom 0.406: 14.25,21 25,21 25,16 20.73,16 14.25,16 14.25,21
  pour Top: 15.75,26.75 15.75,21.25 14.25,21.25 14.25,16 25,16 25,21.25 24.75,21.25 24.75,26.75
  pour Bottom: 15.75,26.75 24.75,26.75 24.75,21.25 25,21.25 25,16 14.25,16 14.25,21.25 15.75,21.25
GPS-LED  (via drill 0.61)
  Top 0.254: v10.16,8.23 10.16,6.6 R6.2 | v10.36,19 v14.83,23.47 | v15.75,31.39 17.17,32.82 25.7,32.82 U1.16
  Bottom 0.254: v10.16,8.23 10.36,8.43 v10.36,19 | v14.83,23.47 15.14,23.77 15.14,24.69 15.75,25.3 v15.75,31.39
HUMIDITY  (via drill 0.61)
  Top 0.254: 79.86,32.61 80.87,32.61 R39.2 | 79.86,32.61 78.54,32.61 R38.1 | v18.49,41.66 18.39,41.66 18.39,39.52 U1.30 | v26.92,55.07 26.92,53.14 29.26,53.14 30.18,52.22 42.98,52.22 43.79,51.41 51,51.41 56.69,57.1 82.8,57.1 86.67,53.24 88.19,53.24 89.92,51.51 89.92,44.09 83.41,44.09 80.67,41.35 80.67,35.56 80.06,35.56 79.86,35.36 79.86,32.61
  Bottom 0.254: v18.49,41.66 25.2,48.36 25.2,53.34 v26.92,55.07
LIGHT  (via drill 0.61)
  Top 0.254: R10.2 62.38,22.86 64.31,22.86 66.14,24.69 C12.1 66.24,24.79 66.24,26.31 65.13,27.43 63.8,27.43 63.8,28.25 U7.1 63.7,28.35 61.57,28.35 v61.57,32.31 | v20.02,36.07 14.22,36.07 U1.36 | v26.82,48.67 29.26,48.67 30.79,50.19 31.29,50.19 32.11,51 43.48,51 43.89,50.6 v54.46,50.6
  Bottom 0.254: v20.02,36.07 22.86,38.91 22.86,44.7 v26.82,48.67 | v54.46,50.6 58.93,46.13 58.93,44.6 60.55,42.98 61.37,42.98 61.37,42.88 61.57,42.67 v61.57,32.31
MISO  (via drill 0.61)
  Top 0.254: v16.87,26.42 16.87,27.84 U1.2 | v14.83,22.25 14.43,21.84 14.02,21.84 13.72,21.54 13.72,16.36 | 13.72,16.36 13.72,15.34 21.03,15.34 22.25,14.12 22.25,12.39 19.41,12.39 19,11.99 U3.SO | v9.45,15.04 10.77,16.36 13.72,16.36
  Bottom 0.254: v16.87,26.42 16.36,25.91 16.36,24.99 15.75,24.38 15.75,23.16 v14.83,22.25 | v9.45,15.04 9.45,14.12 5.59,10.26 JP1.P$1
MOSI  (via drill 0.61)
  Top 0.254: v13.01,28.75 15.14,28.75 15.95,27.94 U1.1 | v12.8,15.44 12.8,14.53 12.29,14.53 U3.SI 12.19,14.33 11.99,14.12 4.37,14.12 3.05,12.8 JP1.4
  Bottom 0.254: v13.01,28.75 12.8,28.55 v12.8,15.44
N$1  (via drill 0.61)
  Top 0.254: v70.41,17.07 68.38,19.1 61.16,19.1 59.13,17.07 58.01,17.07 58.01,18.09 U2.16
  Bottom 0.254: v70.41,17.07 76,11.48 76,11.38 J1.2
N$2
  Top 0.254: U2.15 58.62,18.19 60.66,20.22 68.07,20.22 70.51,22.66 72.34,22.66 72.95,22.05 72.95,21.03 73.97,21.03 79.25,15.75 79.25,11.38 78.13,11.38 J1.3
N$3
  Top 0.254: U1.29 19.2,39.52 19.2,40.64 20.32,40.64 20.73,40.23 20.73,39.52 U1.27 20.83,40.23 21.23,40.64 28.25,40.64 | 28.25,40.64 28.25,42.67 28.04,42.67 L1.2 | 28.25,40.64 28.25,39.93 C1.1
N$4
  Top 0.254: R38.2 78.44,34.54 76.81,36.17 76.81,38.71 78.03,38.71 U12.2
N$5
  Top 0.254: D9.C 19.51,3.86 19.51,7.01 R33.1
N$6
  Top 0.254: D3.A 87.48,50.19 87.38,50.29 84.12,50.29 R11.2
N$7
  Top 0.356: C5.1 71.12,6.1 71.12,10.36 72.34,10.36 L2.2 72.34,10.57 74.68,12.9 75.18,12.9 76,13.72 J1.1
N$8
  Top 0.356: D1.C 11.99,6.5 R6.1
N$9  (via drill 0.61)
  Top 0.254: v58.83,19.61 54.05,19.61 54.05,18.19 U2.22 | v72.34,4.06 72.54,4.27 76.4,4.27 R7.2
  Bottom 0.254: v58.83,19.61 59.54,18.9 59.54,15.04 70.51,4.06 v72.34,4.06
N$10
  Top 0.356: D2.C 78.44,2.03 78.44,4.27 R7.1
N$11  (via drill 0.61)
  Top 0.254: v56.49,13.21 52.83,13.21 52.83,10.87 U2.5 | v58.42,8.23 58.42,7.01 59.13,7.01 Q4.3 59.23,6.91 60.86,6.91 61.67,6.1 R8.2
  Bottom 0.254: v56.49,13.21 58.42,11.28 v58.42,8.23
N$12
  Top 0.254: U2.1 50.19,10.77 50.19,7.92 R9.2
N$13  (via drill 0.61)
  Top 0.356: v57.3,14.43 57.3,18.09 U2.17 | v66.55,5.18 67.87,3.86 71.12,3.86 72.85,2.13 C3.1
  Bottom 0.356: v57.3,14.43 v66.55,5.18
N$14
  Top 0.254: U4.P$1 5.89,49.38 5.99,49.48 7.11,49.48 10.26,52.63 X1.2
N$15  (via drill 0.61)
  Top 0.254: v9.04,50.19 8.74,50.19 7.52,48.97 6.91,48.97 6.71,48.77 5.89,48.77 U4.P$2
  Bottom 0.254: v9.04,50.19 7.82,51.41 7.82,52.63 X1.1
N$16
  Top 0.254: D4.A 8.13,21.03 10.36,21.03 R12.2
N$17
  Top 0.254: D5.A 8.23,32 10.26,32 R13.2
N$18
  Top 0.254: D6.A 8.23,42.37 9.04,43.18 11.07,43.18 R14.2
N$19
  Top 0.254: R15.2 57.91,42.47 54.46,42.47 R16.1 54.36,42.57 54.36,48.16 54.15,48.16 J3.6
N$20
  Top 0.254: R27.2 74.88,38.2 74.88,40.54 R28.1 74.98,40.64 76.61,42.27 76.61,48.26 J6.6
N$21
  Top 0.254: R17.2 51,40.64 47.45,40.64 R18.1
N$22
  Top 0.254: R20.1 28.45,55.98 29.77,54.66 34.04,54.66 35.26,53.44 38.71,53.44 39.73,54.46 J4.3 39.83,54.56 35.15,59.23 29.16,59.23 28.45,58.52 R19.2
N$23
  Top 0.254: R30.1 67.26,42.37 67.46,42.57 71.12,42.57 R29.2
N$24
  Top 0.254: R22.1 28.04,45.41 27.13,46.33 20.52,46.33 19.1,47.75 19.1,49.78 18.8,49.78 18.19,50.39 18.19,51.61 28.14,51.61 R21.2
N$25
  Top 0.254: R23.2 14.83,56.39 14.83,53.95 R24.1 14.94,53.85 15.04,53.75 20.32,53.75 20.52,53.54 23.77,53.54 24.79,54.56 J5.3
N$26
  Top 0.254: 67.36,33.02 U8.4 67.36,33.12 67.36,35.05 67.77,35.05 C13.1
N$27
  Top 0.254: R25.2 12.5,49.48 12.5,51.82 R26.1
N$28
  Top 0.356: C19.1 53.34,36.07 53.44,35.97 55.78,35.97 U9.7
N$29
  Top 0.356: C18.1 71.53,19.71 71.53,16.05 Q2.1 71.42,16.15 68.07,16.15 67.56,16.66 R31.1
N$30
  Top 0.356: C19.2 53.34,38 54.15,37.19 55.78,37.19 U9.6
N$31
  Top 0.356: Q2.3 73.86,15.14 73.86,19 73.97,19 D8.A 74.07,19.1 72.34,20.83 72.24,20.83 71.53,21.54 C18.2
N$32
  Top 0.254: Q1.3 44.91,35.87 45.92,36.88 50.19,36.88 52.43,39.12 57.1,39.12 57.61,39.62 61.67,39.62 62.89,40.84 69.19,40.84 73.66,36.37 74.88,36.37 R27.1
N$33  (via drill 0.61)
  Top 0.254: X2.2 17.27,18.69 19.61,21.03 19.61,22.55 19.81,22.55 C24.1 20.02,22.66 20.62,22.66 v21.44,23.47 | v20.83,29.36 20.83,27.94 U1.7
  Bottom 0.254: v20.83,29.36 21.44,28.75 v21.44,23.47
N$34
  Top 0.254: 59.54,35.87 57.51,35.87 57.51,32.82 R37.1 | 59.54,35.87 60.96,35.87 U9.2 | C27.1 63.7,39.73 63.09,39.12 59.74,39.12 59.54,38.91 59.54,35.87
N$35
  Top 0.254: U1.8 21.64,27.84 21.64,26.72 22.96,25.4 23.57,25.4 C15.1 23.37,25.3 23.37,20.02 22.05,18.69 X2.1
N$36
  Top 0.254: D9.A 17.48,3.76 18.49,2.74 27.13,2.74 30.18,5.79 30.18,11.28 29.57,11.28 28.96,11.89 28.96,14.53 40.84,14.53 U10.21
N$37  (via drill 0.61)
  Top 0.254: v25.5,4.06 24.49,4.06 24.18,3.76 D10.C | v25.5,5.89 24.49,6.91 24.18,6.91 R34.1
  Bottom 0.254: v25.5,4.06 v25.5,5.89
N$38  (via drill 0.61)
  Top 0.254: v22.76,5.08 22.05,5.08 22.05,3.76 D10.A | v29.87,12.19 40.84,12.19 U10.19
  Bottom 0.254: v22.76,5.08 v29.87,12.19
N$39
  Top 0.254: R35.1 45.41,15.85 40.95,15.85 U10.22
N$40
  Top 0.254: Q5.3 48.26,38 45.82,38 Q1.1 45.72,37.9 44.7,36.88 43.99,36.88 43.99,36.58 42.06,34.65 40.23,34.65 40.23,32 R42.2
N$41  (via drill 0.61)
  Top 0.254: v36.68,38 37.9,38 Q3.3 | v45.41,39.42 45.62,39.62 56.9,39.62 57.91,40.64 R15.1
  Bottom 0.254: v36.68,38 45.41,38 v45.41,39.42
N$42
  Top 0.254: R43.2 35.66,32 36.78,33.12 36.98,33.12 36.98,35.87 Q3.1 37.08,35.97 38.1,36.98 39.52,36.98 39.73,36.78 40.34,36.78 41.35,35.76 Q6.3
PWREN~
  Top 0.356: 64.11,11.28 65.33,11.28 R32.2 | 64.11,11.28 59.03,11.28 58.62,10.87 U2.14 | R31.2 67.46,14.73 64.11,11.38 64.11,11.28
RST  (via drill 0.61)
  Top 0.254: v17.37,29.57 18.29,29.57 18.29,27.94 U1.4 | v9.45,38.1 8.53,37.19 8.53,35.05 9.45,35.05 | 9.45,35.05 10.87,35.05 R1.1 | v9.45,34.95 9.45,35.05
  Bottom 0.254: v17.37,29.57 16.66,30.28 16.66,37.29 15.85,38.1 v9.45,38.1 | v9.45,34.95 9.45,32.61 8.94,32.11 8.94,18.69 5.59,15.34 JP1.5
RX1  (via drill 0.61)
  Top 0.254: v29.97,21.64 27.74,21.64 27.74,24.79 25.2,27.33 24.59,27.33 24.08,27.84 U1.11
  Bottom 0.254: v29.97,21.64 28.14,21.64 28.14,14.83 20.02,6.71 14.43,6.71 U13.P$3
RX-BT
  Top 0.254: U10.14 40.95,6.3 41.25,6.6 41.76,6.6 43.38,8.23 45.11,8.23 46.33,9.45 JP2.5
SCK  (via drill 0.61)
  Top 0.254: U3.SCK 12.19,13.11 11.89,12.8 5.59,12.8 JP1.3 | v18.09,26.42 17.68,26.82 17.68,27.84 U1.3 | v15.75,36.98 v17.88,36.98
  Bottom 0.254: v18.09,26.42 18.29,26.62 18.29,34.75 17.88,35.15 v17.88,36.98 | v15.75,36.98 13.11,36.98 13.01,37.08 10.36,37.08 10.36,27.23 9.45,26.31 9.45,16.66 5.59,12.8 JP1.3
SCL  (via drill 0.61)
  Top 0.254: v42.06,26.72 43.18,26.72 43.28,26.62 U5.14 | v11.58,47.95 10.16,47.95 U4.P$6 | v19.1,58.42 19.3,58.22 v26.62,58.22 | U1.19 25.81,35.26 25.91,35.15 29.46,35.15 30.58,34.04 30.58,29.97 33.02,29.97 R3.1 33.02,29.77 40.74,29.77 v41.25,29.26 41.05,29.57 42.16,30.68 v43.38,30.68 | v48.56,25.5 51.61,25.5 51.61,24.18 51.92,23.88 52.53,23.88 52.93,23.47 U11.6
  Bottom 0.254: v42.06,26.72 41.25,27.53 v41.25,29.26 41.25,29.46 38.41,29.46 33.63,34.24 33.63,42.67 32.11,44.2 32.11,52.73 v26.62,58.22 | v11.58,47.95 19.1,55.47 v19.1,58.42 | v43.38,30.68 v48.56,25.5
SDA  (via drill 0.61)
  Top 0.254: v28.96,2.44 28.14,1.63 8.94,1.63 8.94,4.88 5.59,8.23 1.42,8.23 1.42,33.02 4.06,35.66 5.18,35.66 5.18,39.01 4.47,39.73 2.85,39.73 2.85,43.99 4.78,45.92 8.64,45.92 10.06,47.35 U4.P$5 | v51.82,21.03 52.83,22.05 U11.7 53.03,22.15 54.15,22.15 54.15,27.13 51.51,29.77 43.48,29.77 | U1.20 25.81,36.07 32.82,36.07 32.92,36.17 R2.1 33.12,36.27 v34.54,34.85 | 43.48,29.77 43.48,27.74 U5.13 | 43.48,29.77 v42.57,29.77
  Bottom 0.254: v28.96,2.44 50.8,2.44 50.8,20.02 v51.82,21.03 | v34.54,34.85 35.26,34.14 35.26,33.33 38.41,30.18 42.57,30.18 v42.57,29.77
START-BUTTON  (via drill 0.61)
  Top 0.254: v19.1,35.15 18.8,35.15 16.66,33.02 14.33,33.02 14.22,32.92 U1.40 | v19.81,41.76 19.81,44.4 12.9,44.4 12.39,44.91 8.74,44.91 7.11,43.28 4.37,43.28 4.06,43.59 SW1.1
  Bottom 0.254: v19.1,35.15 19.1,41.05 v19.81,41.76
START-LED  (via drill 0.61)
  Top 0.254: v7.01,41.25 7.11,41.25 8.13,40.23 D6.C | v55.98,32.92 55.98,29.97 54.66,29.97 54.36,30.28 45.82,30.28 42.67,33.43 v41.15,33.43 | v35.76,36.07 35.76,37.9 28.35,37.9 v28.25,37.8 | v24.28,31.9 24.79,31.39 25.7,31.39 U1.14
  Bottom 0.254: v7.01,41.25 10.67,44.91 10.67,51.41 16.56,57.3 16.56,58.83 17.37,59.64 39.12,59.64 39.12,49.48 44.6,43.99 48.26,43.99 48.26,43.89 49.68,42.47 61.06,42.47 61.06,38 v55.98,32.92 | v41.15,33.43 36.98,33.43 36.98,34.85 v35.76,36.07 | v28.25,37.8 27.74,37.8 27.64,37.9 25.2,37.9 25.2,32.82 v24.28,31.9
STOP-BUTTON
  Top 0.254: U1.41 14.12,32.11 13.92,32.31 12.6,32.31 11.18,33.73 4.37,33.73 4.06,34.04 SW2.1
STOP-LED  (via drill 0.61)
  Top 0.254: v7.01,30.89 7.11,30.89 8.13,29.87 D5.C | v19.51,52.63 29.06,52.63 v30.58,51.1 | v29.16,34.24 27.03,32.11 25.81,32.11 U1.15
  Bottom 0.254: v7.01,30.89 8.53,32.41 8.53,41.66 v19.51,52.63 | v30.58,51.1 30.58,35.66 v29.16,34.24
TEMP  (via drill 0.61)
  Top 0.254: v41.55,23.06 41.66,23.16 47.65,23.16 U6.2 | v16.05,3.76 16.05,7.62 v13.31,7.62 | v12.7,36.17 13.41,36.88 14.12,36.88 U1.35
  Bottom 0.254: v41.55,23.06 31.6,13.11 27.84,13.11 18.49,3.76 v16.05,3.76 | v13.31,7.62 11.79,9.14 11.79,27.64 10.87,28.55 10.87,34.34 v12.7,36.17
TX1  (via drill 0.61)
  Top 0.254: v26.72,28.75 25.81,29.67 U1.12 | v26.72,22.25 25.81,21.34 25.81,20.12 v29.06,20.12
  Bottom 0.254: v26.72,22.25 v26.72,28.75 | v29.06,20.12 28.65,19.71 28.65,14.63 18.69,4.67 14.43,4.67 U13.P$2
TX-BT
  Top 0.254: U10.13 40.95,5.08 41.35,5.49 43.18,5.49 43.38,5.69 46.84,5.69 47.65,6.5 47.65,10.67 45.01,10.67 43.89,9.55 JP2.6
UNSWPWR
  Top 0.356: D8.C 74.07,22.86 74.07,25.5 74.78,25.5 SW4.2 74.98,25.6 76.61,27.23 79.45,27.23 81.79,29.57 90.02,29.57 90.02,34.34 89.71,34.65 87.48,34.65 87.48,39.83 84.33,42.98 D7.C
VBATT  (via drill 0.61)
  Top 0.356: U4.P$3 5.79,48.06 4.98,48.06 4.67,48.36 4.67,51.31 4.98,51.31 C26.1 5.18,51.41 5.49,51.71 v6.5,51.71 | J7.POS 88.7,46.13 84.94,46.13 84.33,46.74 D7.A 84.12,46.84 81.28,49.68 40.13,49.68 v40.03,49.78
  Bottom 0.356: v6.5,51.71 6.5,53.24 14.12,60.86 40.03,60.86 v40.03,49.78
VINPUT  (via drill 0.61)
  Top 0.356: v10.87,26.52 10.06,26.52 9.35,27.23 R5.2 | 70.71,31.39 70.21,31.39 70,31.19 U8.1 69.8,31.19 68.89,31.19 68.07,32 65.53,32 63.91,33.63 C16.1 63.7,33.73 63.09,34.34 61.06,34.34 U9.1 | 70.71,31.39 70.92,31.6 70.92,32.92 70,32.92 U8.3 | 70.71,31.39 72.54,29.57 72.54,25.6 71.02,25.6 SW4.3 | U9.1 61.16,34.65 62.28,34.65 62.38,34.75 62.59,34.75 62.59,36.27 62.28,36.58 61.57,36.58 61.06,37.08 U9.3 | R37.2 59.33,32.82 60.96,34.44 U9.1
  Bottom 0.356: v10.87,26.52 11.28,26.11 11.28,4.17 13.92,1.52 51.31,1.52 51.31,14.63 57.91,21.23 68.17,21.23 68.17,21.74 70.92,24.49 70.92,25.5 SW4.3
VOLT  (via drill 0.61)
  Top 0.254: R5.1 9.35,25.4 13.21,25.4 R4.2 13.31,25.5 14.53,25.5 v14.83,25.81 | v15.75,35.15 14.33,35.15 14.22,35.26 U1.37
  Bottom 0.254: v15.75,35.15 14.83,34.24 v14.83,25.81
(copper drawn outside any net)
  shapes: $+3v3 area x2, $gnd area x1

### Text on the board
tPlace: 2 | 3 | 1 | 4 | PWR | START | STOP | U10 | CLEAR | PINPoint 4 | beta 4 | GND | BLUETOOTH | RN-41 | BT | JP2 | 3v3 | BT | TALK | GPS | FTDI | XMIT | GND 3.3 5
bPlace: The PINPoint Data Collector | UMASS LOWELL | part of iSENSEproject.org | MACHINE SCIENCE | GPS OUTLINE | BUTTERFLY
